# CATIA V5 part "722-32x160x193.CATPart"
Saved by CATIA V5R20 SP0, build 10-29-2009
Part number: 722-32x160x193
Definition: NONE
Nomenclature: 722-32x160x193
Source: Unknown
Description: 722-32x160x193
Bounding box of the stored display mesh (mm): x -16 to 16, y -16 to 16, z -145 to 48
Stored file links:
  C:\Users\Utente\Desktop\IO LAVORO\3D X SITO CF\X SITO\722\722-32x160x193.CATPart

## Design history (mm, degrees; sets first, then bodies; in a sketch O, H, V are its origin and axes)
Body1 "722-32x160x193" (main body)
  Solid1: solid without history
